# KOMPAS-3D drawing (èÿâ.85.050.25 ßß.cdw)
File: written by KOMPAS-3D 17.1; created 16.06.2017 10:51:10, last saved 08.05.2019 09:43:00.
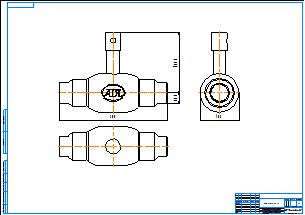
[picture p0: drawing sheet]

Sheet 1: A1, landscape

Title block, sheet 1: name: КШГ.85.050.25 сс; material: Внимание! Данный продукт является объектом авторского права ООО «Торговый Дом АДЛ». / Запрещается изменение, копирование, распространение / (в том числе путем копирования на другие сайты и ресурсы в Интернете) / или любое иное использование информации и объектов без предварительного / согласия правообладателя (ООО «Торговый Дом АДЛ»).; scale: 1:1; sheets: 1; organisation: ООО "Торговый дом АДЛ"; sheet format: A1; stored path: C:\Users\tra\Desktop\2д чертежи\Шаровые краны БИВАЛ\КШ_Бивал_серия_82_85\KOMPAS 2D\КШГ.85.050.25 сс.cdw

Views: Спереди 1, Проекционный вид 2, Проекционный вид 3
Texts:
  Klimkovich
  ADL
Dimensions and other numbers on the sheet: 300; 167,3; 28,5; 108; 1:1; 1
